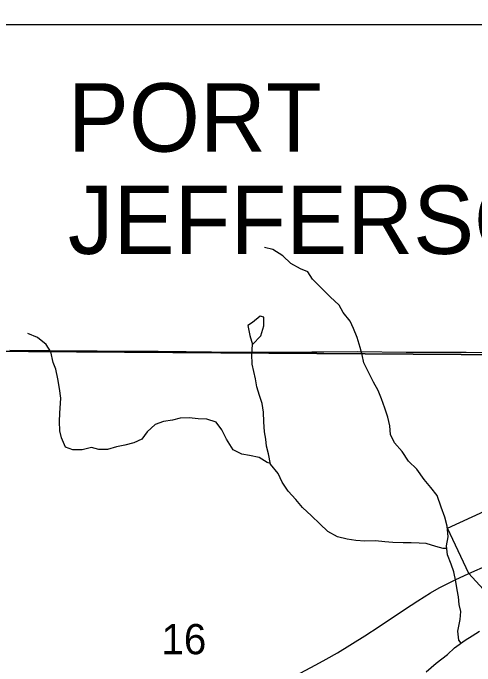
# Model space of a CAD drawing. Extents: x 0 to 1391, y -24 to 440.
# Drawn here: x 586.94 to 599.74, y 326.06 to 344.14 of the extents above; entities that cross this region are included whole.
import ezdxf

# ---------------------------------------------------------------- set-up
doc = ezdxf.new("R2010")
doc.units = 0
for name, color, linetype in [('GM_X_Corporation', 7, 'Continuous'), ('GM_X_Corporation_Text', 7, 'Continuous'), ('GM_X_Minor_Lake', 7, 'Continuous'), ('GM_X_Minor_River', 7, 'Continuous'), ('GM_X_Section', 7, 'Continuous'), ('GM_X_Section_Text', 7, 'Continuous'), ('GM_X_State_Route', 7, 'Continuous'), ('GM_X_Township_Road', 7, 'Continuous'), ('SH_Text', 7, 'Continuous')]:
    doc.layers.add(name, color=color, linetype=linetype)

msp = doc.modelspace()

# ---------------------------------------------------------------- linework, layer by layer
at = {"layer": 'GM_X_Corporation'}
msp.add_lwpolyline([(601.176, 326.864), (599.57, 328.613), (598.982, 329.873), (602.617, 331.542)], dxfattribs=at)
at = {"layer": 'GM_X_Minor_Lake'}
for points in [[(593.576, 334.957), (593.81, 335.202), (593.893, 335.474), (593.892, 335.717), (593.794, 335.743), (593.577, 335.563)], [(593.577, 335.563), (593.445, 335.485), (593.499, 335.21), (593.576, 334.957)]]:
    msp.add_lwpolyline(points, dxfattribs=at)
at = {"layer": 'GM_X_Minor_River'}
for points in [[(599.363, 326.689), (599.296, 326.772), (599.264, 327.024), (599.333, 327.342), (599.347, 327.563), (599.306, 327.762), (599.288, 327.975), (599.248, 328.167), (599.208, 328.396), (599.154, 328.664), (599.083, 328.871), (598.983, 329.133), (598.951, 329.385), (598.996, 329.635), (598.972, 329.925), (598.903, 330.178), (598.803, 330.454), (598.69, 330.777), (598.52, 330.995), (598.336, 331.22), (598.13, 331.507), (597.9, 331.726), (597.724, 331.997), (597.509, 332.231), (597.401, 332.462), (597.384, 332.706), (597.329, 332.943), (597.244, 333.197), (597.152, 333.458), (597.059, 333.681), (596.928, 333.913), (596.798, 334.175), (596.66, 334.452), (596.612, 334.674), (596.564, 334.873), (596.48, 335.15), (596.372, 335.404), (596.286, 335.604), (596.094, 335.845), (595.978, 336.045), (595.725, 336.28), (595.487, 336.515), (595.243, 336.772), (595.111, 336.966), (594.908, 337.054), (594.637, 337.198), (594.415, 337.417), (594.145, 337.591), (593.911, 337.643)], [(594.072, 331.666), (593.988, 331.695), (593.763, 331.831), (593.49, 331.883), (593.286, 331.919), (593.045, 332.039), (592.855, 332.333), (592.724, 332.595), (592.57, 332.805), (592.313, 332.887), (592.07, 332.901), (591.82, 332.93), (591.576, 332.921), (591.362, 332.866), (591.11, 332.826), (590.879, 332.741), (590.661, 332.541), (590.511, 332.339), (590.288, 332.231), (590.035, 332.168), (589.806, 332.121), (589.56, 332.051), (589.317, 332.05), (589.113, 332.108), (588.853, 332.046), (588.594, 332.045), (588.398, 332.118), (588.283, 332.373), (588.242, 332.572), (588.233, 332.823), (588.239, 333.059), (588.265, 333.469), (588.226, 333.737), (588.18, 334.012), (588.125, 334.272), (588.054, 334.464), (587.986, 334.755), (587.861, 334.956), (587.615, 335.153), (587.352, 335.266)], [(598.961, 329.308), (598.858, 329.311), (598.654, 329.362), (598.39, 329.445), (598.2, 329.457), (597.972, 329.47), (597.751, 329.468), (597.462, 329.476), (597.242, 329.496), (596.984, 329.518), (596.687, 329.511), (596.444, 329.532), (596.201, 329.568), (595.937, 329.636), (595.666, 329.78), (595.443, 329.991), (595.213, 330.21), (594.96, 330.445), (594.776, 330.663), (594.568, 330.897), (594.4, 331.144), (594.284, 331.383), (594.077, 331.64), (594.016, 331.931), (593.969, 332.145), (593.943, 332.336), (593.91, 332.542), (593.894, 332.817), (593.886, 333.084), (593.846, 333.321), (593.768, 333.543), (593.698, 333.789), (593.658, 334.003), (593.61, 334.21), (593.57, 334.416), (593.562, 334.691), (593.576, 334.957)], [(598.391, 325.896), (598.671, 326.133), (598.982, 326.376), (599.176, 326.554), (599.471, 326.767), (599.664, 326.892), (599.865, 327.016)]]:
    msp.add_lwpolyline(points, dxfattribs=at)
at = {"layer": 'GM_X_Section'}
for points in [[(603.709, 343.811), (603.356, 334.656), (583.361, 334.79), (583.446, 343.811)], [(583.361, 334.79), (603.356, 334.656), (603.288, 328.097), (603.227, 328.091), (603.044, 328.026), (602.839, 327.969), (602.679, 327.911), (602.526, 327.853), (602.388, 327.779), (602.274, 327.706), (602.12, 327.602), (601.998, 327.514), (601.883, 327.432), (601.782, 327.343), (601.606, 327.202), (601.467, 327.068), (601.313, 326.935), (601.182, 326.801), (600.989, 326.561), (600.873, 326.435), (600.749, 326.3), (600.618, 326.136), (600.494, 326.002)]]:
    msp.add_lwpolyline(points, dxfattribs=at)
at = {"layer": 'GM_X_State_Route'}
for points in [[(599.57, 328.613), (600.113, 328.855), (600.691, 329.114), (601.1, 329.294), (601.906, 329.649), (602.161, 329.76), (602.702, 329.998), (603.327, 330.275), (603.428, 330.32), (604.083, 330.613), (604.406, 330.755), (604.803, 330.933), (605.298, 331.154), (605.96, 331.447), (606.508, 331.692), (607.115, 331.966), (607.746, 332.259), (608.161, 332.444), (608.476, 332.581), (608.907, 332.778), (608.922, 332.785), (609.441, 333.008), (610.153, 333.326), (610.513, 333.51)], [(594.763, 325.785), (595.333, 326.089), (595.616, 326.245), (595.93, 326.422), (596.692, 326.888), (597.086, 327.147), (597.79, 327.616), (598.163, 327.863), (598.51, 328.082), (598.749, 328.217), (599.194, 328.44), (599.57, 328.613)]]:
    msp.add_lwpolyline(points, dxfattribs=at)
at = {"layer": 'GM_X_Township_Road'}
msp.add_lwpolyline([(586.848, 334.8), (587.805, 334.792), (587.929, 334.791), (588.612, 334.787), (589.27, 334.782), (590.959, 334.772), (591.742, 334.767), (593.147, 334.747), (594.337, 334.749), (595.218, 334.753), (595.554, 334.754), (596.494, 334.761), (597.835, 334.747), (598.53, 334.743), (599.498, 334.743), (600.753, 334.74)], dxfattribs=at)
at = {"layer": 'SH_Text'}
msp.add_lwpolyline([(574.209, 353.247), (615.184, 353.247), (615.184, 343.811), (574.209, 343.811)], close=True, dxfattribs=at)

# ---------------------------------------------------------------- texts
at = {"layer": 'GM_X_Corporation_Text'}
for s, p in [('PORT', (588.461, 340.299)), ('JEFFERSON', (588.461, 337.466))]:
    msp.add_text(s, height=1.8939, rotation=0, dxfattribs=at).set_placement(p)
at = {"layer": 'GM_X_Section_Text'}
msp.add_text('16', height=0.8371, rotation=0, dxfattribs=at).set_placement((591.052, 326.381))

doc.saveas('drawing.dxf')
